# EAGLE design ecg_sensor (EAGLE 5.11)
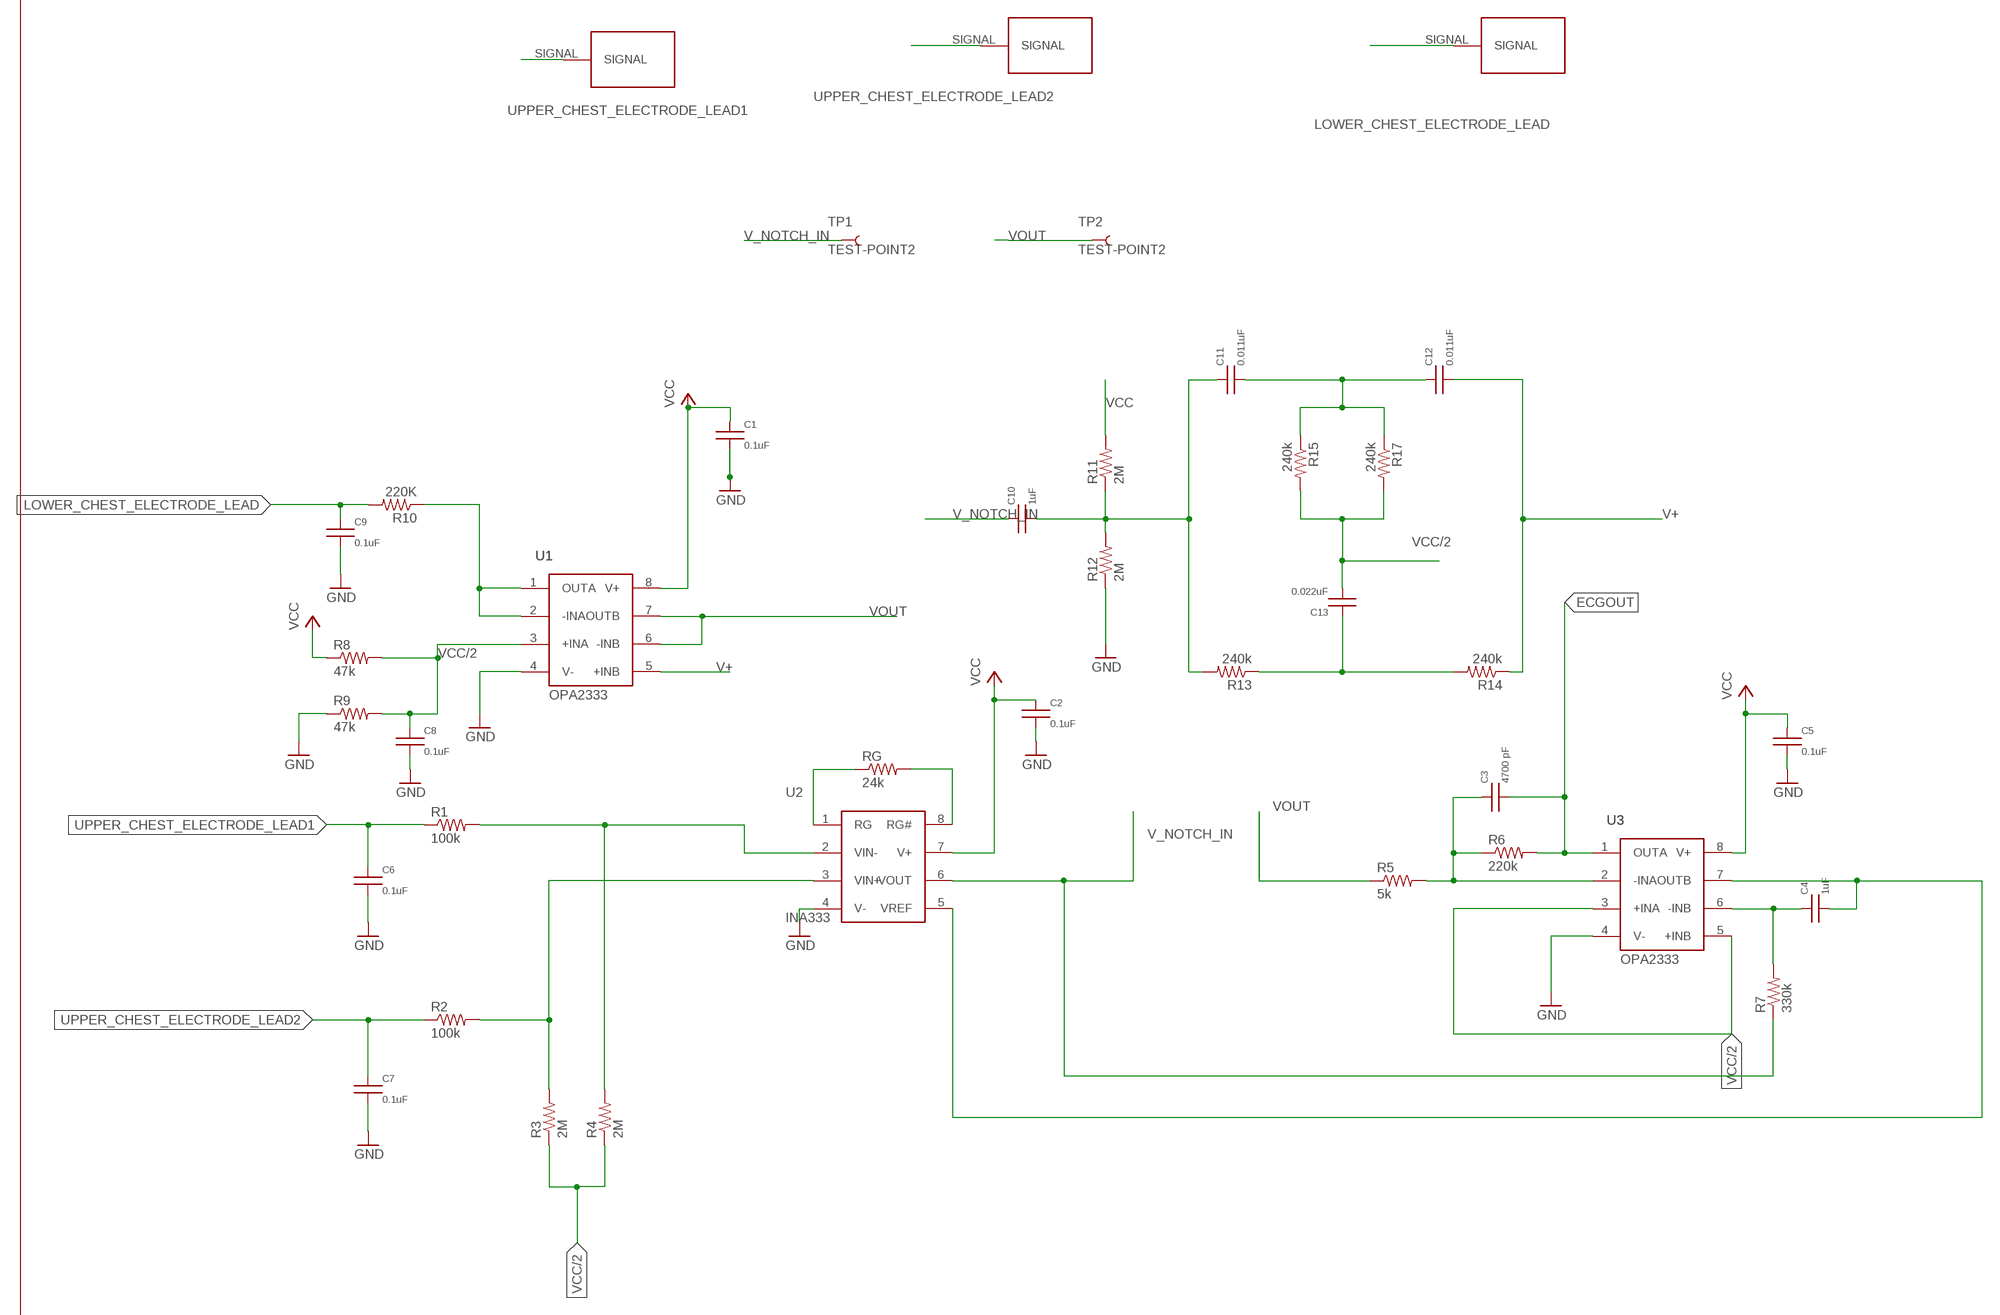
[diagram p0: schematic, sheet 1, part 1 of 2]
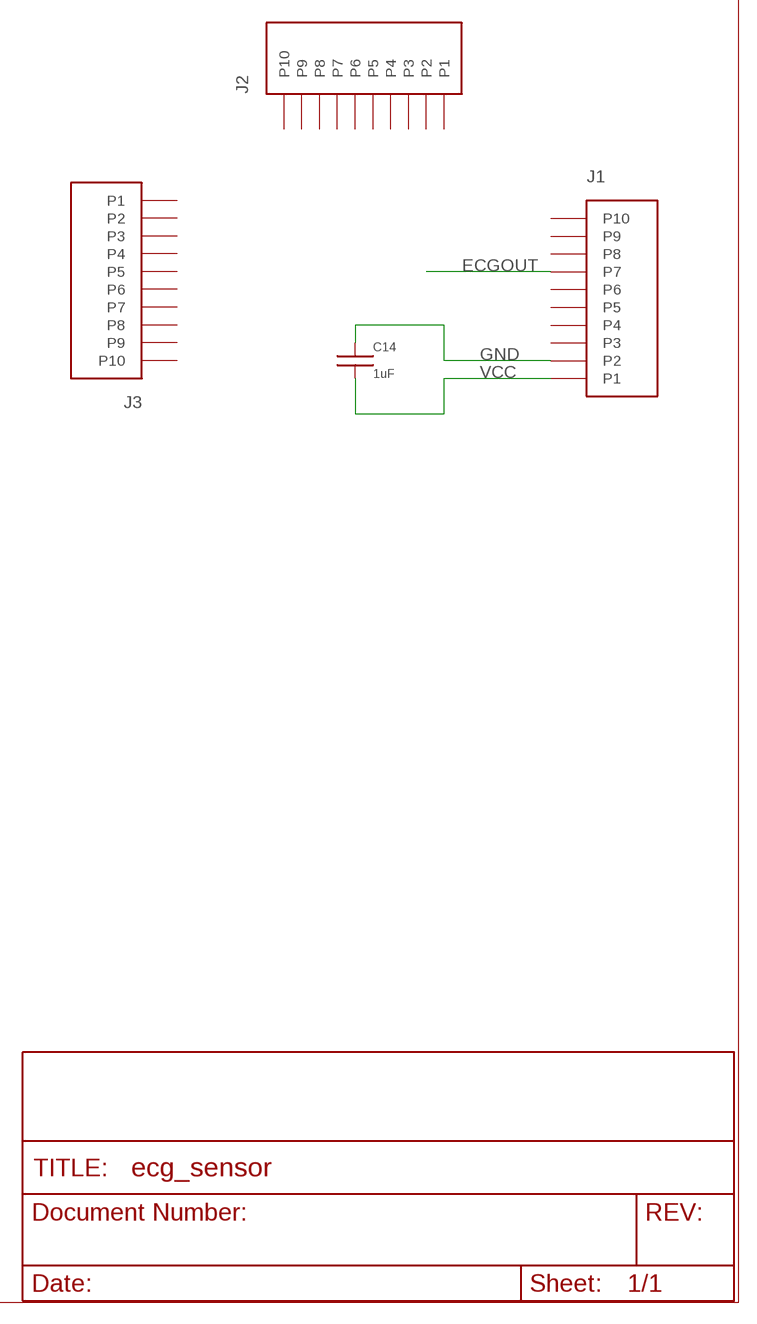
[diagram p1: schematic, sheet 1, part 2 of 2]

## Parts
BLACK  PLASTICJACKNEW  [PLASTICJACKNEW]
C1  0.1uF  C0603  [C0603]
C2  0.1uF  C0603  [C0603]
C3  4700 pF  C0603  [C0603]
C4  1uF  C0603  [C0603]
C5  0.1uF  C0603  [C0603]
C6  0.1uF  C0603  [C0603]
C7  0.1uF  C0603  [C0603]
C8  0.1uF  C0603  [C0603]
C9  0.1uF  C0603  [C0603]
C10  1uF  C0603  [C0603]
C11  0.011uF  C1206  [C1206]
C12  0.011uF  C1206  [C1206]
C13  0.022uF  C1206  [C1206]
C14  1uF  C0603  [C0603]
J1  HEADER10POS  [10PIN2MMHEADER]
J2  HEADER10POS  [10PIN2MMHEADER]
J3  HEADER10POS  [10PIN2MMHEADER]
R1  100k  R-US_R0603  [R0603]
R2  100k  R-US_R0603  [R0603]
R3  2M  R-US_R0603  [R0603]
R4  2M  R-US_R0603  [R0603]
R5  5k  R-US_R0603  [R0603]
R6  220k  R-US_R0603  [R0603]
R7  330k  R-US_R0603  [R0603]
R8  47k  R-US_R0603  [R0603]
R9  47k  R-US_R0603  [R0603]
R10  220K  R-US_R0603  [R0603]
R11  2M  R-US_R0603  [R0603]
R12  2M  R-US_R0603  [R0603]
R13  240k  R-US_R0603  [R0603]
R14  240k  R-US_R0603  [R0603]
R15  240k  R-US_R0603  [R0603]
R17  240k  R-US_R0603  [R0603]
RED  PLASTICJACKNEW  [PLASTICJACKNEW]
RG  24k  R-US_R0603  [R0603]
TP1  TEST-POINT2  [PAD.02X.02]
TP2  TEST-POINT2  [PAD.02X.02]
U1  OPA2333  [SOIC]
U2  INA333  [MSOP8]
U3  OPA2333  [SOIC]
WHITE  PLASTICJACKNEW  [PLASTICJACKNEW]

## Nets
ECGOUT: C3.2 J1.P7 R6.2 U3.1(OUTA)
GND: C1.2 C2.2 C5.2 C6.2 C7.2 C8.2 C9.2 C14.1 J1.P2 R9.1 R12.1 U1.4(V-) U2.4(V-) U3.4(V-)
LOWER_CHEST_ELECTRODE_LEAD: BLACK.SIGNAL C9.1 R10.2
N$2: R10.1 U1.1(OUTA) U1.2(-INA)
N$4: RG.1 U2.1(RG)
N$5: RG.2 U2.8(RG#)
N$6: R1.2 R4.2 U2.2(VIN-)
N$7: C11.2 C12.1 R15.1 R17.1
N$8: R2.2 R3.2 U2.3(VIN+)
N$10: C10.2 C11.1 R11.1 R12.2 R13.2
N$12: C13.1 R13.1 R14.2
N$13: C3.1 R5.2 R6.1 U3.2(-INA)
N$17: C4.1 R7.2 U3.6(-INB)
UPPER_CHEST_ELECTRODE_LEAD1: C6.1 R1.1 RED.SIGNAL
UPPER_CHEST_ELECTRODE_LEAD2: C7.1 R2.1 WHITE.SIGNAL
V+: C12.2 R14.1 U1.5(+INB)
V_NOTCH_IN: C10.1 R7.1 TP1.P$1 U2.6(VOUT)
VCC: C1.1 C2.1 C5.1 C14.2 J1.P1 R8.1 R11.2 U1.8(V+) U2.7(V+) U3.8(V+)
VCC/2: C8.1 C13.2 R3.1 R4.1 R8.2 R9.2 R15.2 R17.2 U1.3(+INA) U3.3(+INA) U3.5(+INB)
VOUT: R5.1 TP2.P$1 U1.6(-INB) U1.7(OUTB)
VREF: C4.2 U2.5(VREF) U3.7(OUTB)
Unconnected: J1.P3 J1.P4 J1.P5 J1.P6 J1.P8 J1.P9 J1.P10 J2.P1 J2.P2 J2.P3 J2.P4 J2.P5 J2.P6 J2.P7 J2.P8 J2.P9 J2.P10 J3.P1 J3.P2 J3.P3 J3.P4 J3.P5 J3.P6 J3.P7 J3.P8 J3.P9 J3.P10

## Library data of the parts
BLACK RED WHITE = sonal:PLASTICJACKNEW
C1-C14 = umich:C
J1-J3 = hijack:HEADER10POS: Fits 3M 950510-6102-AR
R1-R15 R17 RG = rcl:R-US_: RESISTOR, American symbol
TP1 TP2 = SparkFun:TEST-POINT
U1 U3 = sonal:OPA2333
U2 = sonal:INA333

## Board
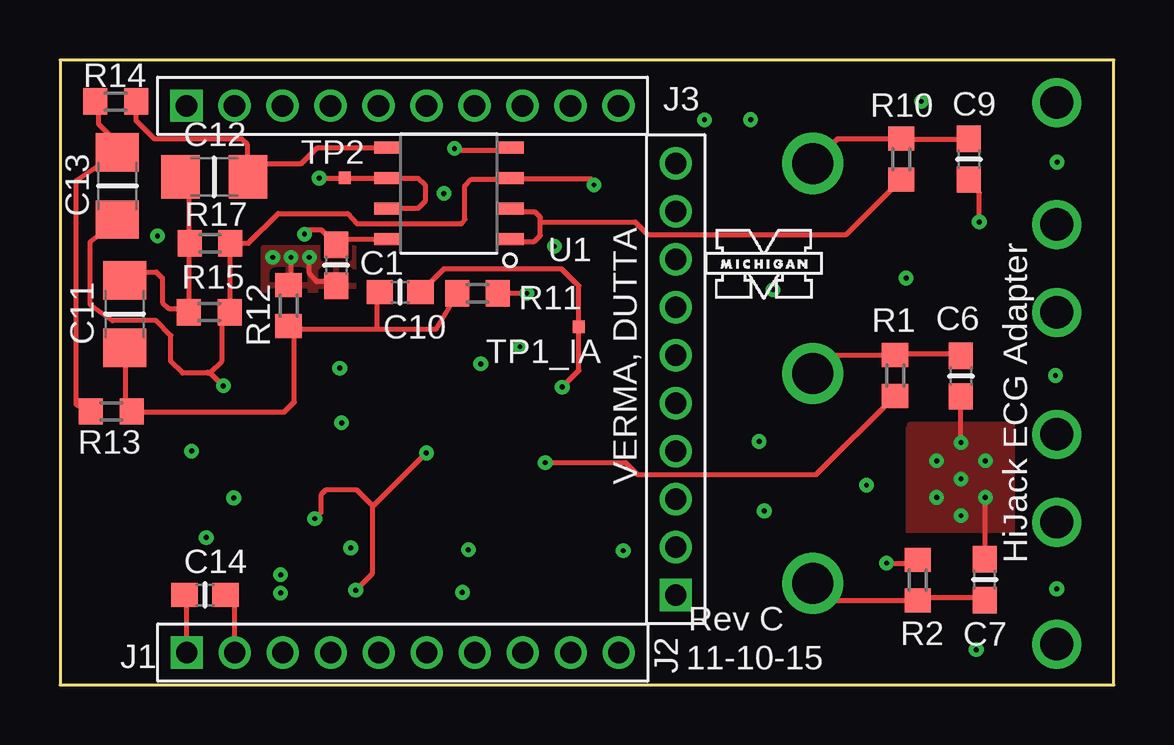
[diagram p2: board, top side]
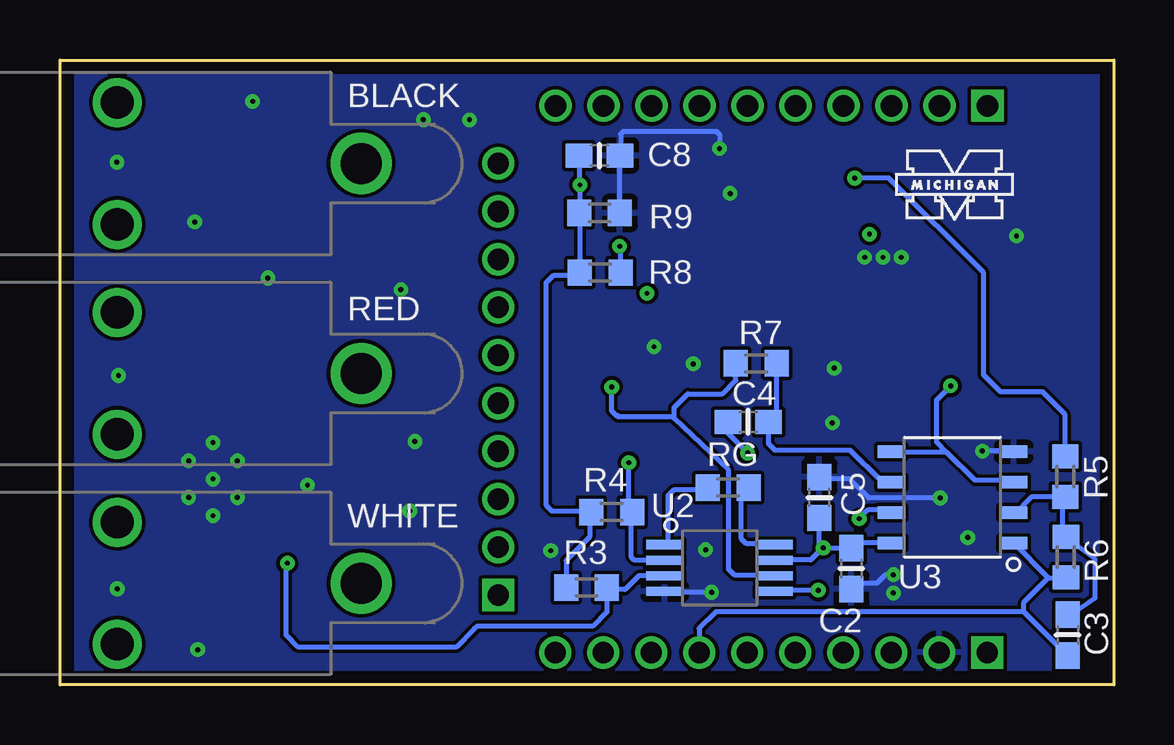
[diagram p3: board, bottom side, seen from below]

Size 43.92 x 26.06 mm. Coordinates in mm from the lower left corner, seen from the top.
Outline: 0,0 43.92,0 43.92,26.06 0,26.06 0,0
Copper layers (1+2*15+16): Top 0.0178mm / dielectric 0.3048mm / $GND 0.0356mm / dielectric 0.7112mm / $VCC 0.0356mm / dielectric 0.3048mm / Bottom 0.0178mm
Design rules "SSC-EAGLE-4Lyr_v1.0.0.3": minimum track width 6mil, minimum drill 8mil, track to track 6mil, track to pad 6mil, pad to pad 6mil, via to via 6mil, smd to smd 6mil, copper to edge 20mil, drill to drill 16mil, minimum pad ring 8mil, minimum via ring 8mil, stop-mask expansion 3mil, vias tented up to drill 0mil, thermal gap 10mil

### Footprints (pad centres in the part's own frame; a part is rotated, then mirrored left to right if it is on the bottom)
PLASTICJACKNEW = drill 1.359 pad 2.032 round: P$1 2.286,2.54; P$2 2.286,-2.54 | drill 1.702 pad 2.54 round: SIGNAL -7.874,0
C0603 = smd 1.1 x 1: 1 -0.85,0; 2 0.85,0
C1206 = smd 1.6 x 1.8: 1 -1.4,0; 2 1.4,0
10PIN2MMHEADER = drill 0.89 pad 1.346 square: P1 -9,0 | drill 0.89 pad 1.346 round: P2 -7,0; P3 -5,0; P4 -3,0; P5 -1,0; P6 1,0; P7 3,0; P8 5,0; P9 7,0; P10 9,0
R0603 = smd 1 x 1.1: 1 -0.85,0; 2 0.85,0
PAD.02X.02 = smd 0.508 x 0.508: P$1 0,0
SOIC = smd 0.51 x 1.143: 1 -1.905,-2.55; 2 -0.635,-2.55; 3 0.635,-2.55; 4 1.905,-2.55; 5 1.905,2.55; 6 0.635,2.55; 7 -0.635,2.55; 8 -1.905,2.55
MSOP8 = smd 0.38 x 1.524: 1 -0.975,-2.292; 2 -0.325,-2.292; 3 0.325,-2.292; 4 0.975,-2.292; 5 0.975,2.292; 6 0.325,2.292; 7 -0.325,2.292; 8 -0.975,2.292

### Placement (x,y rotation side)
BLACK  39.24,21.74 180 bottom
C1  11.51,17.5 270 top
C2  10.95,4.85 270 bottom
C3  1.93,2.08 270 bottom
C4  15.24,10.97 180 bottom
C5  12.27,7.82 90 bottom
C6  37.54,12.88 270 top
C7  38.53,4.39 90 top
C8  21.44,22.07 0 bottom
C9  37.87,21.92 270 top
C10  14.17,16.38 180 top
C11  2.69,15.47 90 top
C12  6.43,21.18 0 top
C13  2.39,20.8 270 top
C14  6.05,3.76 180 top
J1  14.28,1.35 0 top
J2  25.66,12.75 90 top
J3  14.27,24.15 0 top
R1  34.8,12.9 270 top
R2  35.74,4.37 90 top
R3  21.98,4.06 0 bottom
R4  20.93,7.21 0 bottom
R5  2.03,8.69 270 bottom
R6  2.01,5.33 270 bottom
R7  14.91,13.41 0 bottom
R8  21.41,17.2 180 bottom
R9  21.44,19.69 180 bottom
R10  35.05,21.92 90 top
R11  17.4,16.33 0 top
R12  9.52,15.82 270 top
R13  2.13,11.4 0 top
R14  2.32,24.33 180 top
R15  6.22,15.54 0 top
R17  6.25,18.41 0 top
RED  39.24,12.99 180 bottom
RG  16.08,8.23 0 bottom
TP1  21.62,14.94 0 top
TP2  11.86,21.14 0 top
U1  16.21,20.5 90 top
U2  16.43,4.88 270 bottom
U3  6.73,7.82 90 bottom
U$1  [UMICH]  26.8,15.9 0 top
U$2  [UMICH]  9.17,19.2 0 bottom
WHITE  39.24,4.24 180 bottom

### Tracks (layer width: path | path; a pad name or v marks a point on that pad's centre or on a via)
ECGOUT
  Bottom 0.203: 3.76,3.05 1.93,1.22 C3.2 | 4.17,5.89 U3.1 2.73,4.47 | R6.2 2.13,4.47 2.73,4.47 | 3.76,3.05 10.87,3.05 10.88,3.06 16.58,3.06 17.28,2.36 J1.P7 | 2.73,4.47 3.76,3.44 3.76,3.05
GND  (via drill 0.2)
  Top 0.203: C6.2 37.69,11.99 37.54,11.84 v37.54,10.11 | 38.51,5.28 C7.2 38.56,5.27 v38.56,7.82 | C9.2 37.9,20.93 38.3,20.52 v38.3,19.3 | 6.6,3.45 6.81,3.66 C14.1 | C14.1 7.01,3.86 7.23,3.86 | U1.4 18.59,22.56 18.97,22.3 16.51,22.3 v16.44,22.37 | R12.1 9.63,16.67 v9.63,17.83 | C1.2 11.51,16.71 11.4,16.82 10.69,16.82 10.39,17.17 v10.39,17.83 | J1.P2 7.28,3.37 C14.1
  Bottom 0.203: v16.76,3.86 18.39,3.86 U2.4 | R9.1 20.63,19.71 20.63,21.95 C8.2 20.42,22.15 20.56,22.28 20.56,22.97 20.45,23.08 16.56,23.08 16.41,22.93 16.41,22.39 v16.44,22.37 16.45,22.18 | v5.49,9.75 4.17,9.75 U3.4 | v9.2,4.6 9.53,4.6 9.86,4.27 10.68,4.27 C2.2 | v7.24,7.8 10.23,7.8 11.03,8.6 12.2,8.6 C5.2
  other vias: 36.53,9.35 37.54,8.59 38.56,9.35 36.53,7.82 37.54,7.06 9.19,3.84 8.86,17.83 17.02,5.64 19.17,14.1 11.65,13.21 6.1,6.15 4.06,18.72 11.73,10.93 29.34,7.26 38.18,1.47 41.53,4.01 41.48,12.9 41.55,21.8 28.78,23.57 29.72,16.48 35.26,16.97 33.6,8.33 29.13,10.15 35.89,24.33 17.53,13.39 15.99,20.5 26.86,23.56 23.47,5.6
  pour Top: 35.41,10.9 39.73,10.9 39.73,6.4 35.31,6.4 35.31,10.72 35.36,10.72 35.36,10.87
  pour Bottom: 8.59,4.9 9.86,4.9 9.86,3.51 8.59,3.51
  pour Top: 8.46,18.24 8.46,16.46 12.27,16.46 12.27,18.24
  pour Bottom: 43.74,25.76 43.74,25.7 43.69,25.7 43.69,0.2 0.36,0.2 0.28,25.81
LOWER_CHEST_ELECTRODE_LEAD
  Top 0.203: C9.1 37.69,22.76 R10.2 32.4,22.77 BLACK.SIGNAL
N$2
  Top 0.203: 18.8,18.69 U1.1 18.86,18.49 19.76,18.49 20.02,18.75 20.02,19.3 | U1.2 18.8,19.71 19.81,19.71 20.02,19.51 20.02,19.3 | 35.05,20.93 R10.1 32.77,18.79 24.49,18.79 23.98,19.3 20.02,19.3
N$4
  Bottom 0.203: RG.1 16.97,8.13 18.35,8.13 18.59,7.88 18.59,5.99 U2.1
N$5
  Bottom 0.203: U2.8 14.53,5.89 15.32,5.89 15.52,6.1 15.52,7.93 RG.2 15.14,8.13
N$6  (via drill 0.2)
  Top 0.203: 34.47,11.99 34.65,11.99 R1.2 31.52,8.78 24.06,8.78 23.56,9.27 v20.22,9.27
  Bottom 0.203: R4.2 20.02,7.11 | v20.22,9.27 20.22,7.32 R4.2 | U2.2 19.98,5.2 20.11,5.33 20.11,7.18 R4.2
N$7
  Top 0.203: C11.2 2.74,16.87 2.9,16.87 3.25,17.22 4.01,17.22 4.27,16.97 4.27,15.95 4.52,15.7 5.22,15.7 R15.1 5.39,15.65 5.39,18.49 R17.1 5.39,18.69 5.39,20.93 5.18,21.13 C12.1
N$8  (via drill 0.2)
  Top 0.203: v34.44,5.08 35.66,5.08 R2.2
  Bottom 0.203: 18.59,4.47 U2.3 19.8,4.55 20.37,3.99 21.05,3.99 R3.2 21.13,3.05 21.72,2.46 26.51,2.46 26.52,2.46 26.67,2.31 | v34.44,5.08 34.49,5.03 34.49,2.08 33.99,1.58 27.41,1.58 26.67,2.31 | 26.67,2.31 26.67,2.34
N$10
  Top 0.203: C11.1 2.74,14.02 2.74,11.79 2.95,11.58 R13.2 3.15,11.38 9.35,11.38 9.77,11.8 9.77,14.73 arc90 R12.2 9.65,14.85 13.22,14.85 | 16.36,16.26 R11.1 16.55,16.3 15.68,14.85 13.22,14.85 | C10.2 13.22,16.28 13.22,14.85
N$12
  Top 0.203: R13.1 0.69,11.68 0.69,21.03 2.34,22.15 C13.1 2.34,22.35 2.24,22.45 2.24,22.76 1.61,23.39 1.61,24.19 R14.2 1.45,24.35
N$13
  Bottom 0.203: C3.1 1.93,2.85 0.79,3.63 0.79,5.26 1.93,6.1 R6.1 2.13,6.3 2.13,7.72 R5.2 3.44,7.84 4.17,7.11 U3.2
N$17
  Bottom 0.203: U3.6 9.45,8.53 9.73,8.53 10.98,9.79 14.12,9.79 14.39,10.06 C4.1 | C4.1 14.53,10.97 | C4.1 14.25,10.83 | C4.1 14.06,10.97 R7.2
UPPER_CHEST_ELECTRODE_LEAD1
  Top 0.203: R1.1 34.85,13.82 37.49,13.82 C6.1 | R1.1 34.65,13.61 | RED.SIGNAL 32.13,13.75 R1.1
UPPER_CHEST_ELECTRODE_LEAD2
  Top 0.203: R2.1 35.87,3.66 38.51,3.66 C7.1 | R2.1 35.66,3.66 | WHITE.SIGNAL 32.09,3.52 R2.1
V+
  Top 0.203: 8.03,21.74 10.06,21.74 10.72,22.4 U1.5 | 8.03,21.74 8.03,21.34 C12.2 | 7.42,21.34 7.82,21.34 C12.2 | 8.03,21.74 8.03,21.97 | R14.1 3.17,23.54 3.95,22.76 7.57,22.76 7.81,22.52 7.81,21.2 C12.2
V_NOTCH_IN  (via drill 0.2)
  Top 0.203: C10.1 15.99,17.35 20.9,17.35 21.62,16.64 TP1.P$1 21.62,13.11 v20.93,12.42
  Bottom 0.203: 18.33,11.12 16.05,8.97 16.05,4.83 15.8,4.57 14.42,4.57 U2.6 | 18.33,11.12 18.39,11.18 20.6,11.18 | 20.6,11.18 20.65,11.23 20.73,11.23 20.93,11.43 v20.93,12.42 20.93,12.27 | 20.68,11.18 20.65,11.2 20.63,11.18 20.6,11.18 | R7.1 15.76,12.69 16.31,12.14 17.75,12.14 18.33,11.57 18.33,11.12
VCC  (via drill 0.2)
  Top 0.203: R11.2 18.19,16.46 | 13.72,18.49 U1.8 11.75,18.59 C1.1 11.51,18.36 10.9,18.97 10.36,18.97 v10.19,18.8 | C14.2 5.18,3.66 5.23,3.66 | C14.2 5.39,3.86 | R11.2 18.19,16.26 | R11.2 v19.46,16.33 | J1.P1 5.28,3.67 C14.2
  Bottom 0.203: 14.33,5.28 U2.7 14.35,5.16 13.54,5.16 13.48,5.21 12.64,5.21 12.14,5.72 v12.12,5.72 | 20.42,17.07 R8.1 20.56,18.25 v20.6,18.29 | U3.8 10.76,5.92 10.96,5.72 C2.1 12.1,5.7 v12.12,5.72 | v12.12,5.72 12.12,5.93 | C5.1 12.27,5.87 v12.12,5.72
VCC/2  (via drill 0.2)
  Top 0.203: v22.25,20.85 22.12,21.11 18.78,21.11 U1.3 18.7,21.08 17.15,21.08 16.87,20.8 16.87,19.41 16.74,19.23 12.37,19.23 11.99,19.66 9.09,19.66 7.85,18.42 R17.2 7.1,15.55 R15.2 | C13.2 2.34,19.3 1.27,18.49 1.27,15.85 2.18,15.19 4.01,15.19 4.62,14.58 4.62,13.49 5.11,13.01 6.17,13.01 | R15.2 7.01,15.44 | R15.2 6.88,15.36 | R15.2 6.76,15.23 6.76,13.51 6.25,13.01 6.17,13.01 | 6.17,13.01 6.15,13.03 6.25,13.03 v6.81,12.47
  Bottom 0.203: U3.3 4.37,8.53 5.79,8.53 6.96,9.7 | 9.25,9.75 U3.5 9.26,9.7 6.96,9.7 | R4.1 21.84,7.11 21.84,6.18 22.83,5.19 R3.1 | C8.1 22.25,21.95 v22.25,20.85 | R4.1 21.84,7.32 | v22.25,20.85 22.25,19.71 R9.2 22.25,19.51 22.25,17.27 R8.2 22.45,17.07 23.37,17.07 23.68,16.76 23.68,7.51 23.42,7.26 21.82,7.26 R4.1 | v22.25,20.85 22.25,20.93 | 6.96,9.7 7.39,10.13 7.39,11.89 v6.81,12.47
VOUT  (via drill 0.2)
  Top 0.203: U1.6 14.94,21.13 15.21,20.85 15.21,20.17 14.91,19.86 U1.7 | U1.6 13.61,21.13 13.61,21.16 | U1.6 11.9,21.13 TP2.P$1 v10.8,21.14
  Bottom 0.203: R5.1 2.03,11.28 2.97,12.22 4.72,12.22 5.44,12.93 5.44,17.2 9.38,21.14 v10.8,21.14
VREF  (via drill 0.2)
  Top 0.203: v10.62,6.93 10.87,7.19 10.87,7.93 11.07,8.13 12.37,8.13 13.03,7.47 | 13.03,7.47 13.06,7.47 v15.27,9.68 | 13.03,7.47 13.03,4.66 v12.32,3.95
  Bottom 0.203: 14.34,3.96 U2.5 14.36,3.94 12.32,3.94 v12.32,3.95 | U3.7 9.45,7.32 10.24,7.32 v10.62,6.93 | C4.2 16.09,10.5 v15.27,9.68 15.29,9.65

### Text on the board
tPlace: TP2 | TP1_IA | VERMA, DUTTA | HiJack ECG Adapter | Rev C | 11-10-15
